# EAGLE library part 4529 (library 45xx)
Dual 4-channel analog DATA SELECTOR
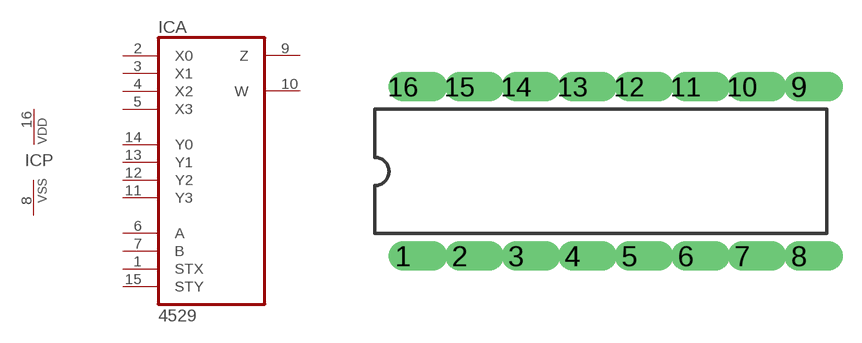
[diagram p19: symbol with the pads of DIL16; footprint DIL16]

Designator prefix IC; gates A=4529 P=PWRN

## 4529N  [DIL16]
1  A:STX  in
2  A:X0  in
3  A:X1  in
4  A:X2  in
5  A:X3  in
6  A:A  in
7  A:B  in
8  P:VSS  pwr
9  A:Z  hiz
10  A:W  hiz
11  A:Y3  in
12  A:Y2  in
13  A:Y1  in
14  A:Y0  in
15  A:STY  in
16  P:VDD  pwr

## Footprint DIL16 (pad centres in mm)
Dual In Line
drill 0.813 offset: 1 -8.89,-3.81; 2 -6.35,-3.81; 3 -3.81,-3.81; 4 -1.27,-3.81; 5 1.27,-3.81; 6 3.81,-3.81; 7 6.35,-3.81; 8 8.89,-3.81; 9 8.89,3.81; 10 6.35,3.81; 11 3.81,3.81; 12 1.27,3.81; 13 -1.27,3.81; 14 -3.81,3.81; 15 -6.35,3.81; 16 -8.89,3.81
